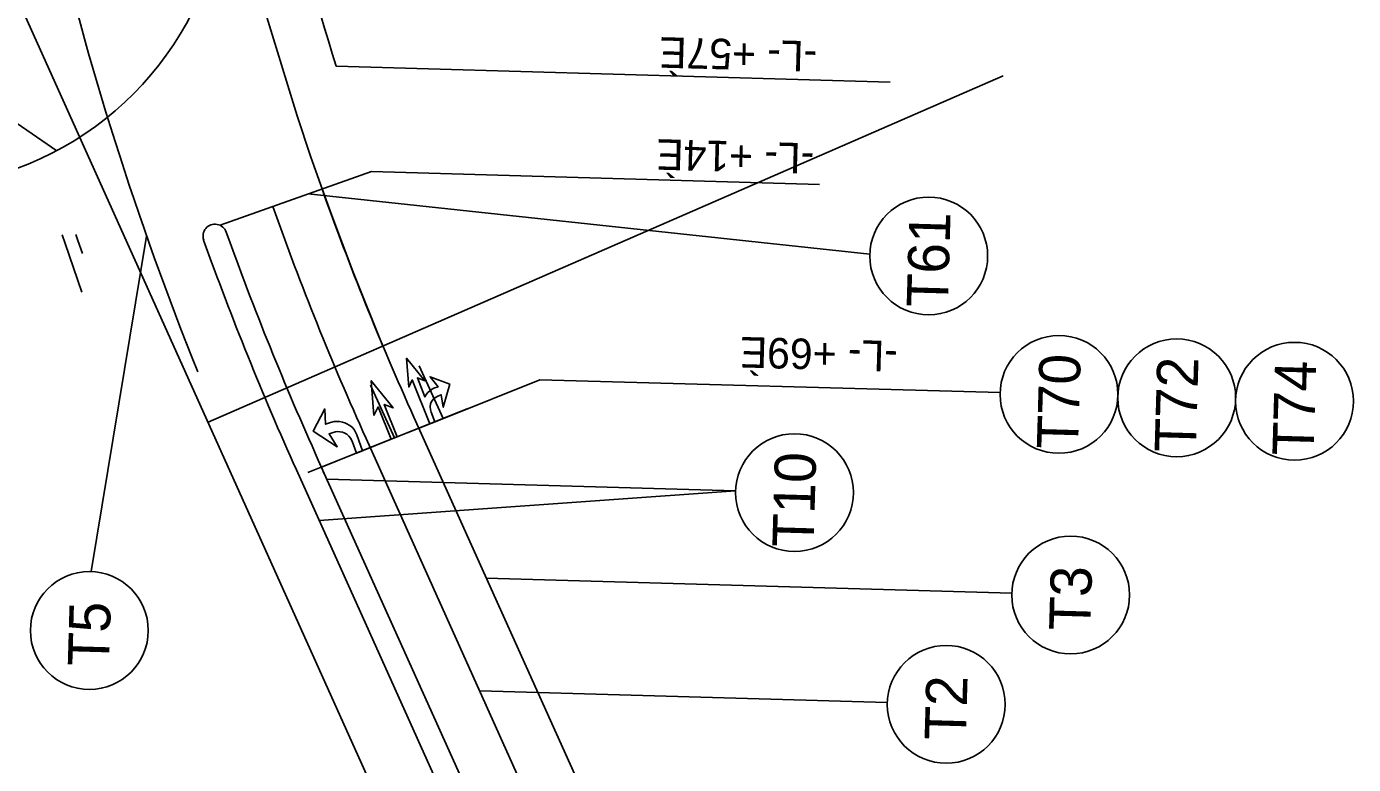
# Model space of a CAD drawing. Extents: x 1657109 to 2100937, y 684916 to 883211.
# Drawn here: x 2097693.3 to 2097997.3, y 685728.9 to 685898 of the extents above; entities that cross this region are included whole.
import ezdxf

# ---------------------------------------------------------------- set-up
doc = ezdxf.new("R2010")
doc.units = 0
for name, color, linetype in [('Old_Level_63', 7, 'Continuous'), ('Prop CMT Pvmt Gravel', 7, 'Continuous'), ('Prop Conc 1ft 6in Curb and Gutter', 7, 'Continuous'), ('Prop Conc 2ft 6in Curb and Gutter', 7, 'Continuous'), ('Prop Conc Curb and Gutter', 7, 'Continuous'), ('Prop Dimension', 7, 'Continuous'), ('Prop DSN Text', 7, 'Continuous'), ('Prop EOT', 7, 'Continuous'), ('Prop Lane Arrow CELL', 7, 'Continuous'), ('Prop Lane Lines', 7, 'Continuous'), ('Prop Paved Shoulder', 7, 'Continuous'), ('Prop Sign E Chevron Right', 7, 'Continuous'), ('Scratch_Level_5', 7, 'Continuous')]:
    doc.layers.add(name, color=color, linetype=linetype)

# ---------------------------------------------------------------- blocks, each defined once
blk = doc.blocks.new('SRARR')
at = {"layer": 'Old_Level_63'}
blk.add_lwpolyline([(0, 0.5), (8.667, 0.5), (7.667, 1.583), (12.75, 0), (7.667, -1.583), (8.667, -0.5), (4.895, -0.5), (5.26, -0.958), (5.468, -1.31), (5.628, -1.759), (5.708, -2.127), (5.772, -2.592), (5.75, -3.417), (8, -2.75), (5.417, -5.583), (1.917, -2.917), (4.167, -3.417), (4.155, -2.768), (4.138, -2.384), (4.042, -1.999), (3.866, -1.663), (3.674, -1.326), (3.322, -0.99), (2.889, -0.734), (2.425, -0.574), (1.896, -0.493), (0, -0.5)], close=True, dxfattribs=at)
blk.add_lwpolyline([(0, 0.5), (8.667, 0.5), (7.667, 1.583), (12.75, 0), (7.667, -1.583), (8.667, -0.5), (4.895, -0.5), (5.26, -0.958), (5.468, -1.31), (5.628, -1.759), (5.708, -2.127), (5.772, -2.592), (5.75, -3.417), (8, -2.75), (5.417, -5.583), (1.917, -2.917), (4.167, -3.417), (4.155, -2.768), (4.138, -2.384), (4.042, -1.999), (3.866, -1.663), (3.674, -1.326), (3.322, -0.99), (2.889, -0.734), (2.425, -0.574), (1.896, -0.493), (0, -0.5)], close=True, dxfattribs=at)

msp = doc.modelspace()

# ---------------------------------------------------------------- linework, layer by layer
at = {"layer": 'Prop CMT Pvmt Gravel'}
for p, q in [((2097642.82, 685909.02), (2097700.19, 685869.55)), ((2097764.23, 685888.91), (2097891.16, 685885.23)), ((2097772.31, 685864.8), (2097874.92, 685861.82)), ((2097886.49, 685845.82), (2097757.79, 685859.64)), ((2097708.08, 685773.08), (2097720.8, 685849.99)), ((2097762.09, 685794.3), (2097855.74, 685791.58)), ((2097855.74, 685791.58), (2097760.35, 685784.77)), ((2097798.62, 685771.62), (2097919.01, 685768.12)), ((2097797.1, 685745.77), (2097890.49, 685743.06))]:
    msp.add_line(p, q, dxfattribs=at)
msp.add_lwpolyline([(2097768.85, 685800.24), (2097777.59, 685803.73), (2097788.79, 685808.2), (2097810.91, 685817.02), (2097916.32, 685814.1)], dxfattribs=at)
for centre in [(2097899.98, 685845.43), (2097929.82, 685813.7), (2097956.8, 685812.92), (2097983.79, 685812.13), (2097869.23, 685791.19), (2097932.5, 685767.73), (2097707.68, 685759.59), (2097903.99, 685742.66)]:
    msp.add_circle(centre, 13.5, dxfattribs=at)
at = {"layer": 'Prop Conc 1ft 6in Curb and Gutter'}
msp.add_line((2097808.82, 685719.73), (2097771.08, 685803.58), dxfattribs=at)
msp.add_arc((2098415.1, 686093.44), 706.25, 199.57973, 204.23092, dxfattribs=at)
at = {"layer": 'Prop Conc 2ft 6in Curb and Gutter'}
msp.add_arc((2097665.53, 685934.68), 73.78, 287.7359, 0.5072, dxfattribs=at)
at = {"layer": 'Prop Conc Curb and Gutter'}
for p, q in [((2097797.05, 685716.63), (2097760.13, 685798.66)), ((2097792.84, 685712.58), (2097755.12, 685796.4))]:
    msp.add_line(p, q, dxfattribs=at)
for centre, radius, start, end in [((2097736.46, 685849.97), 2.75, 19.6141, 199.736), ((2098415.1, 686093.44), 723.75, 199.73603, 204.23092), ((2098415.1, 686093.44), 718.25, 199.73563, 204.23092)]:
    msp.add_arc(centre, radius, start, end, dxfattribs=at)
at = {"layer": 'Prop Dimension'}
for p, q in [((2097788.75, 685808.18), (2097783.26, 685820.23)), ((2097777.59, 685803.73), (2097772.11, 685815.78)), ((2097757.76, 685795.82), (2097794.4, 685810.44)), ((2097783.17, 685805.95), (2097794.33, 685810.4)), ((2097772.01, 685801.5), (2097783.17, 685805.95))]:
    msp.add_line(p, q, dxfattribs=at)
for points in [[(2097704.58, 685850.36), (2097705.06, 685848.96), (2097706.07, 685846.03)], [(2097761.43, 685795.62), (2097760.86, 685797.05), (2097772, 685801.5)]]:
    msp.add_lwpolyline(points, dxfattribs=at)
at = {"layer": 'Prop DSN Text'}
msp.add_lwpolyline([(2097701.43, 685850.29), (2097702.13, 685848.26), (2097705.95, 685837.14)], dxfattribs=at)
at = {"layer": 'Prop EOT'}
msp.add_line((2097860.8, 685633.46), (2097782.02, 685808.51), dxfattribs=at)
msp.add_arc((2098415.1, 686093.44), 694.25, 199.57973, 204.23092, dxfattribs=at)
at = {"layer": 'Prop Lane Arrow CELL'}
for radius, start, end in [(682.25, 181.10817, 197.44435), (735.75, 193.16901, 201.91468)]:
    msp.add_arc((2098415.1, 686093.44), radius, start, end, dxfattribs=at)
at = {"layer": 'Prop Lane Lines'}
msp.add_line((2097737.61, 685852.46), (2097772.31, 685864.8), dxfattribs=at)
at = {"layer": 'Prop Paved Shoulder'}
for points in [[(2097768.85, 685800.24), (2097770.26, 685800.75), (2097768.95, 685804.4), (2097768.67, 685805.06), (2097768.39, 685805.54), (2097768.01, 685806.03), (2097767.6, 685806.41), (2097767.23, 685806.67), (2097766.66, 685806.99), (2097766.19, 685807.18), (2097765.65, 685807.36), (2097764.97, 685807.49), (2097764.46, 685807.51), (2097763.8, 685807.47), (2097762.94, 685807.28), (2097761.8, 685806.87), (2097761.6, 685810.38), (2097758.92, 685805.29), (2097764.47, 685801.71), (2097762.61, 685804.63), (2097763.55, 685804.97), (2097764.09, 685805.14), (2097764.63, 685805.18), (2097765.07, 685805.14), (2097765.66, 685805.03), (2097766.09, 685804.88), (2097766.64, 685804.55), (2097767.1, 685804.11), (2097767.49, 685803.65), (2097767.87, 685802.95)], [(2097768.85, 685800.24), (2097770.26, 685800.75), (2097768.94, 685804.4), (2097768.66, 685805.06), (2097768.39, 685805.53), (2097768.01, 685806.03), (2097767.6, 685806.4), (2097767.23, 685806.67), (2097766.66, 685806.99), (2097766.19, 685807.18), (2097765.65, 685807.36), (2097764.97, 685807.49), (2097764.46, 685807.51), (2097763.8, 685807.47), (2097762.94, 685807.28), (2097761.8, 685806.87), (2097761.6, 685810.38), (2097758.92, 685805.29), (2097764.46, 685801.71), (2097762.61, 685804.63), (2097763.55, 685804.97), (2097764.09, 685805.14), (2097764.63, 685805.18), (2097765.07, 685805.14), (2097765.66, 685805.03), (2097766.09, 685804.88), (2097766.64, 685804.55), (2097767.1, 685804.11), (2097767.49, 685803.65), (2097767.87, 685802.95)]]:
    msp.add_lwpolyline(points, close=True, dxfattribs=at)
at = {"layer": 'Prop Sign E Chevron Right'}
for p, q in [((2097817.26, 685624.22), (2097510.8, 686305.14)), ((2097734.86, 685807.3), (2097917.06, 685886.7))]:
    msp.add_line(p, q, dxfattribs=at)
msp.add_lwpolyline([(2097774.95, 685824.77), (2097768.11, 685841.69), (2097763.2, 685854.69), (2097761, 685860.78), (2097758.45, 685868.09), (2097755.26, 685877.58), (2097748.31, 685900.14), (2097742.63, 685920.91), (2097734.98, 685954.09), (2097731.95, 685969.82), (2097729.85, 685982.04), (2097728.33, 685991.83), (2097727.13, 686000.31), (2097725.21, 686015.75), (2097723.9, 686028.46), (2097723.18, 686036.72), (2097722.54, 686045.08), (2097721.93, 686054.74), (2097721.58, 686061.62)], dxfattribs=at)
at = {"layer": 'Scratch_Level_5'}
msp.add_lwpolyline([(2097772.87, 685808.84), (2097773.82, 685810.84), (2097776.79, 685803.41), (2097778.18, 685803.96), (2097775.22, 685811.39), (2097777.28, 685810.6), (2097772.25, 685816.81)], close=True, dxfattribs=at)
msp.add_lwpolyline([(2097772.87, 685808.84), (2097773.82, 685810.84), (2097776.79, 685803.41), (2097778.18, 685803.96), (2097775.22, 685811.39), (2097777.28, 685810.6), (2097772.25, 685816.81)], close=True, dxfattribs=at)

# ---------------------------------------------------------------- block references
at = {"layer": 'Prop CMT Pvmt Gravel', "xscale": 1.25, "yscale": 1.2499999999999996, "rotation": 111.75168141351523}
msp.add_blockref('SRARR', (2097786.26, 685807.19), dxfattribs=at)

# ---------------------------------------------------------------- texts
at = {"layer": 'Prop CMT Pvmt Gravel'}
for s, height, rotation, p in [('-L- +57È', 7, 178.4251, (2097874.52, 685894.6)), ('-L- +14È', 7, 178.4251, (2097873.84, 685871.22)), ('T61', 9.45, 88.3348, (2097904.36, 685833.55)), ('-L- +69È', 7, 178.4251, (2097893, 685825.89)), ('T70', 9.45, 88.3348, (2097934.18, 685801.07)), ('T72', 9.45, 88.3348, (2097961.17, 685800.36)), ('T74', 9.45, 88.3348, (2097988.15, 685799.54)), ('T10', 9.45, 88.3348, (2097873.59, 685778.55)), ('T3', 9.45, 88.3348, (2097936.99, 685759.48)), ('T5', 9.45, 88.3348, (2097712.17, 685751.3)), ('T2', 9.45, 88.3348, (2097908.47, 685734.36))]:
    msp.add_text(s, height=height, rotation=rotation, dxfattribs=at).set_placement(p)

doc.saveas('drawing.dxf')
